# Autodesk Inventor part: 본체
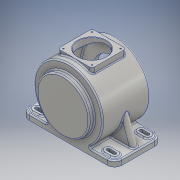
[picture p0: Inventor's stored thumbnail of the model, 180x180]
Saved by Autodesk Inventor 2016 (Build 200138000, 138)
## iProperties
Created: 2015-06
Part Number: 본체
Material: 알루미늄 6061
Document SubType Name: Modeling
Designer: Administrator
Density: 2.7 g/cm^3
Appearance: 알루미늄 - 평지
Mass: 3261.14 g
Surface Area: 2303.44 cm^2
Volume: 1207.83 cm^3
Author: Administrator
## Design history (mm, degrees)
sketch "스케치1"
  geometry: L1 (-115, 59)-(115, 59); L2 (115, 59)-(115, -59); L3 (115, -59)-(-115, -59); L4 (-115, -59)-(-115, 59); 3 further points
  constraints: 8 end point, 2 midpoint, 2 parallel, 1 horizontal, 1 horizontal alignment, 1 perpendicular, 1 vertical alignment
  dimensions: "d0" = 230 distance between parallel lines of L2 L4; "d1" = 118 distance between parallel lines of L3 L1
extrude "돌출1" new body sketch "스케치1" distance "d2" = 14; taper "d3" = 0 deg
sketch "스케치2"
  geometry: L1 (115, 0)-(-115, 0) reference; L2 (115, 0)-(115, 14) reference; L3 (-115, 14)-(115, 14) reference; L4 (-115, 0)-(-115, 14) reference; C1 r 85 at (0, 85); 2 further points
  constraints: 1 centre point, 1 midpoint, 1 vertical alignment
  dimensions: "d4" = 85 distance from line of L1 C1.centre; "d5" = 170 diameter of C1
extrude "돌출2" join sketch "스케치2" stored distance "d6" = 118; taper "d7" = 0 deg
sketch "스케치3"
  geometry: C1 r 65 at (115, 85); A1 r 85 centre (115, 85) between (161.733, 14) and (68.267, 14) reference; 1 further point
  constraints: 1 centre point, 1 coincident
  dimensions: "d8" = 130 diameter of C1
extrude "돌출3" join sketch "스케치3" distance "d9" = 13; taper "d10" = 0 deg
sketch "스케치4"
  geometry: L1 (230, -14)-(161.733, -14) reference; L2 (230, 0)-(230, -14) reference; L3 (0, 0)-(230, 0) reference; L4 (0, 0)-(0, -14) reference; L5 (68.267, -14)-(0, -14) reference; C1 r 65 at (115, -85); A1 r 85 centre (115, -85) between (68.267, -14) and (161.733, -14) reference; 1 further point
  constraints: 1 centre point, 1 coincident
  dimensions: "d11" = 130 diameter of C1
extrude "돌출4" join sketch "스케치4" distance "d12" = 3; taper "d13" = 0 deg
sketch "스케치5"
  geometry: L1 (-115, 14)-(-46.733, 14) reference; L2 (-84.87, 80.297)-(-109, 14); L3 (-115, 14)-(-46.733, 14) reference; L4 (-115, 0)-(-115, 14) reference; L5 (115, 0)-(-115, 0) reference; L6 (115, 0)-(115, 14) reference; L7 (46.733, 14)-(115, 14) reference; C1 r 65 at (0, 85) reference; A1 r 85 centre (0, 85) between (46.733, 14) and (-46.733, 14) reference; A2 r 85 centre (0, 85) between (46.733, 14) and (-46.733, 14) reference; 1 further point
  constraints: 2 end point, 1 point on circle, 1 point on line
  dimensions: "d14" = 110 deg angle of L2 L1; "d15" = 6 distance from line of L2.end L4
feature "리브1" sketch "스케치5" dims "d16" = 1, "d17" = 15, "d18" = 0, "d19" = 0, "d20" = 1, "d21" = 1
node "작업 평면1"
sketch "스케치6"
  geometry: L1 (42.5, 42.5)-(-42.5, 42.5); L2 (-42.5, 42.5)-(-42.5, -42.5); L3 (-42.5, -42.5)-(42.5, -42.5); L4 (42.5, -42.5)-(42.5, 42.5); 3 further points
  constraints: 8 end point, 2 midpoint, 2 parallel, 2 perpendicular, 1 horizontal, 1 horizontal alignment, 1 vertical alignment
  dimensions: "d23" = 85 distance between parallel lines of L2 L4
extrude "돌출5" join sketch "스케치6" stored distance "d24" = 3; taper "d25" = 0 deg
sketch "스케치7"
  geometry: C1 r 35 at (0, 0); 1 further point
  constraints: 1 centre point, 1 coincident
  dimensions: "d26" = 70 diameter of C1
sketch "스케치8"
  geometry: L1 (-42.5, 158.612)-(42.5, 158.612) reference; L2 (42.5, 158.612)-(42.5, 158.612) reference; L3 (42.5, 158.612)-(-42.5, 158.612) reference; L4 (-42.5, 158.612)-(-42.5, 158.612) reference; L5 (-7.5, 80.297)-(7.5, 80.297) reference; L6 (7.5, 80.297)-(7.5, 14) reference; L7 (59, 14)-(7.5, 14) reference; L8 (59, 14)-(59, 14) reference; L9 (7.5, 14)-(59, 14) reference; L10 (7.5, 14)-(7.5, 80.297) reference; L11 (7.5, 80.297)-(-7.5, 80.297) reference; L12 (-7.5, 80.297)-(-7.5, 14) reference; L13 (-59, 14)-(-7.5, 14) reference; L14 (-59, 14)-(-59, 14) reference; L15 (-7.5, 14)-(-59, 14) reference; L16 (-7.5, 14)-(-7.5, 80.297) reference; L17 (-72, 150)-(-72, 20) reference; L18 (62, 20)-(62, 150) reference; L19 (-72, 85)-(62, 85); L20 (62, 132.5)-(51, 132.5); L21 (51, 132.5)-(51, 159); L22 (48, 162)-(-48, 162); L23 (-51, 159)-(-51, 117.911); L24 (-49.268, 115.192)-(-47.5, 114.368); L25 (-47.5, 114.368)-(-47.5, 108.5); L26 (-47.5, 108.5)-(-61.2, 108.5); L27 (-61.5, 108.2)-(-61.5, 100); L28 (-61.5, 100)-(-61.5, 100); L29 (-64.5, 97)-(-64.5, 85); A1 r 0.3 centre (-61.2, 108.2) between (-61.2, 108.5) and (-61.5, 108.2); A2 r 3 centre (-61.5, 97) between (-61.5, 100) and (-64.5, 97); A3 r 3 centre (-48, 159) between (-48, 162) and (-51, 159); A4 r 3 centre (48, 159) between (51, 159) and (48, 162); A5 r 3 centre (-48, 117.911) between (-51, 117.911) and (-49.268, 115.192); 2 further points
  constraints: 22 end point, 10 point on circle, 10 tangent, 7 perpendicular, 5 centre point, 4 point on line, 2 midpoint, 1 equal radius, 1 horizontal, 1 vertical
  dimensions: "d27" = 11 distance between parallel lines of L18 L21; "d28" = 95 diameter of L20 L19; "d29" = 154 diameter of L22 L19; "d30" = 102 distance between parallel lines of L21 L23; "d31" = 62 diameter of point (-51, 116) L19; "d32" = 115 deg angle of L24 L23; "d33" = 3 distance between parallel lines of L27 L29; "d34" = 14 distance between parallel lines of L25 L27; "d35" = 30 diameter of L28 L19; "d36" = 47 diameter of L26 L19; "d37" = 3.5 distance between parallel lines of L25 L23; "d38" = 0.3 radius of A1; "d39" = 3 radius of A2; "d40" = 3 radius of A3; "d96" = 3 radius of A5
revolve "회전1" sketch "스케치8" stored, may be unused: angle "d41" = 90 deg
extrude "돌출6" cut sketch "스케치7" distance "d42" = 50; taper "d43" = 0 deg
sketch "스케치9"
  geometry: L1 (42.5, -42.5)-(-42.5, -42.5) reference; L2 (42.5, 42.5)-(42.5, -42.5) reference; L3 (-42.5, -42.5)-(-42.5, 42.5) reference; L4 (-42.5, 42.5)-(42.5, 42.5) reference; L5 (-35.5, -35.5)-(35.5, -35.5); L6 (35.5, -35.5)-(35.5, 35.5); L7 (35.5, 35.5)-(-35.5, 35.5); L8 (-35.5, 35.5)-(-35.5, -35.5); 5 further points
  constraints: 8 end point, 4 coincident, 3 other
  dimensions: "d44" = 71 distance between parallel lines of L8 L6
hole "구멍1" sketch "스케치9" at (35.5, -35.5), (-35.5, -35.5), (-35.5, 35.5), (35.5, 35.5) diameter "d45" = 3.242; stored, may be unused: countersink angle "d49" = 90 deg, drill point angle "d51" = 118 deg; dims "d46" = 10, "d47" = 4, "d48" = 2, "d50" = 13
chamfer "모따기1" distance "d52" = 1; stored, may be unused: second distance "d53" = 2, angle "d54" = 45 deg
fillet "모깎기1" dims "d56" = 7
sketch "스케치10"
  geometry: L1 (115, 59)-(115, -59) reference; L2 (115, -59)-(-115, -59) reference; L3 (-115, -59)-(-115, 59) reference; L4 (-115, 59)-(115, 59) reference; L5 (-97, 41)-(-81, 41); L6 (-97, 32)-(-81, 32); L7 (-81, 50)-(-97, 50); L8 (-115, 0)-(115, 0); L9 (-115, 59)-(115, 59) reference; L10 (0, 59)-(0, -59); L11 (115, -59)-(-115, -59) reference; L12 (-97, -41)-(-81, -41); L13 (-81, -50)-(-97, -50); L14 (-97, -32)-(-81, -32); L15 (97, -32)-(81, -32); L16 (97, -41)-(81, -41); L17 (81, -50)-(97, -50); L18 (97, 32)-(81, 32); L19 (81, 50)-(97, 50); L20 (97, 41)-(81, 41); A1 r 9 centre (-97, 41) between (-97, 50) and (-97, 32); A2 r 9 centre (-81, 41) between (-81, 32) and (-81, 50); A3 r 9 centre (-97, -41) between (-97, -32) and (-97, -50); A4 r 9 centre (-81, -41) between (-81, -50) and (-81, -32); A5 r 9 centre (81, -41) between (81, -32) and (81, -50); A6 r 9 centre (97, -41) between (97, -50) and (97, -32); A7 r 9 centre (81, 41) between (81, 50) and (81, 32); A8 r 9 centre (97, 41) between (97, 32) and (97, 50); 5 further points
  constraints: 36 end point, 21 symmetric about line, 16 point on circle, 8 centre point, 5 midpoint, 4 tangent, 1 horizontal, 1 parallel, 6 other
  dimensions: "d57" = 16 distance of L5.end L5.start; "d58" = 18 distance between parallel lines of L6 L7; "d59" = 18 distance from line of L5.start L3; "d60" = 18 distance from line of point (-89, 41) L4
extrude "돌출7" join sketch "스케치10" distance "d61" = 3; taper "d62" = 0 deg
sketch "스케치11"
  geometry: L1 (115, 59)-(115, -59) reference; L2 (115, -59)-(-115, -59) reference; L3 (-115, -59)-(-115, 59) reference; L4 (-115, 59)-(115, 59) reference; L5 (-97, 50)-(-81, 50) reference; L6 (-81, 32)-(-97, 32) reference; L7 (-81, -50)-(-97, -50) reference; L8 (-97, -32)-(-81, -32) reference; L9 (-46.733, -7.5)-(-109, -7.5) reference; L10 (-109, -7.5)-(-109, 7.5) reference; L11 (-109, 7.5)-(-46.733, 7.5) reference; L12 (-46.733, 7.5)-(-46.733, 59) reference; L13 (-46.733, 59)-(-115, 59) reference; L14 (-115, 59)-(-115, -59) reference; L15 (-115, -59)-(-46.733, -59) reference; L16 (-46.733, -59)-(-46.733, -7.5) reference; L17 (97, -50)-(81, -50) reference; L18 (81, -32)-(97, -32) reference; L19 (81, 50)-(97, 50) reference; L20 (97, 32)-(81, 32) reference; L21 (109, -7.5)-(46.733, -7.5) reference; L22 (46.733, -7.5)-(46.733, -59) reference; L23 (46.733, -59)-(115, -59) reference; L24 (115, -59)-(115, 59) reference; L25 (115, 59)-(46.733, 59) reference; L26 (46.733, 59)-(46.733, 7.5) reference; L27 (46.733, 7.5)-(109, 7.5) reference; L28 (109, 7.5)-(109, -7.5) reference; L29 (-81, 45)-(-97, 45); L30 (-97, 37)-(-81, 37); L31 (-81, -45)-(-97, -45); L32 (-97, -37)-(-81, -37); L33 (97, 45)-(81, 45); L34 (81, 37)-(97, 37); L35 (97, -45)-(81, -45); L36 (81, -37)-(97, -37); A1 r 9 centre (-97, 41) between (-97, 50) and (-97, 32) reference; A2 r 9 centre (-81, 41) between (-81, 32) and (-81, 50) reference; A3 r 9 centre (-81, -41) between (-81, -50) and (-81, -32) reference; A4 r 9 centre (-97, -41) between (-97, -32) and (-97, -50) reference; A5 r 9 centre (97, -41) between (97, -50) and (97, -32) reference; A6 r 9 centre (81, -41) between (81, -32) and (81, -50) reference; A7 r 9 centre (81, 41) between (81, 50) and (81, 32) reference; A8 r 9 centre (97, 41) between (97, 32) and (97, 50) reference; A9 r 4 centre (-97, 41) between (-97, 45) and (-97, 37); A10 r 4 centre (-81, 41) between (-81, 37) and (-81, 45); A11 r 4 centre (-81, -41) between (-81, -45) and (-81, -37); A12 r 4 centre (-97, -41) between (-97, -37) and (-97, -45); A13 r 4 centre (81, 41) between (81, 45) and (81, 37); A14 r 4 centre (97, 41) between (97, 37) and (97, 45); A15 r 4 centre (97, -41) between (97, -45) and (97, -37); A16 r 4 centre (81, -41) between (81, -37) and (81, -45); 1 further point
  constraints: 16 end point, 16 point on circle, 8 centre point, 3 equal radius, 12 other
  dimensions: "d63" = 8 distance between parallel lines of L30 L29
extrude "돌출11" cut sketch "스케치11" stored distance "d86" = 124; taper "d87" = 0 deg
sketch "스케치12"
  geometry: C1 r 65 at (0, 0) reference; A1 r 55 centre (0, 0) between (0, -55) and (55, 0); 3 further points
  constraints: 4 point on circle, 2 horizontal alignment, 2 vertical alignment, 1 centre point, 1 coincident
  dimensions: "d66" = 110 diameter of A1
hole "구멍2" sketch "스케치12" at (0, -55), (55, 0), (0, 55), (-55, 0) diameter "d67" = 3.242; stored, may be unused: countersink angle "d71" = 90 deg, drill point angle "d73" = 118 deg; dims "d68" = 10, "d69" = 4, "d70" = 2, "d72" = 13
sketch "스케치13"
  geometry: L1 (-115, 0)-(115, 0) reference; L2 (0, 85)-(85, 85); L3 (0, 85)-(77.036, 120.923); A1 r 85 centre (0, 85) between (46.733, 14) and (-46.733, 14) reference; 2 further points
  constraints: 4 end point, 2 point on circle, 1 coincident, 1 horizontal
  dimensions: "d74" = 25 deg angle of L2 L3
node "작업 평면2"
sketch "스케치14"
  geometry: 3 further points
  constraints: 1 coincident, 1 other
extrude "돌출9" join sketch "스케치14" stored distance "d75" = 0.5; taper "d76" = 0 deg
chamfer "모따기2" distance "d80" = 1; stored, may be unused: second distance "d81" = 2, angle "d82" = 45 deg
fillet "모깎기3" dims "d84" = 18
fillet "모깎기5" dims "d88" = 3
fillet "모깎기6" dims "d89" = 7.5
fillet "모깎기8" dims "d91" = 3
fillet "모깎기9" dims "d92" = 3
fillet "모깎기10" dims "d93" = 3
fillet "모깎기11" dims "d94" = 3
fillet "모깎기12" dims "d95" = 3
fillet "모깎기13" dims "d97" = 3
node "솔리드1"
mirror "대칭1"
node "투영된 루프1"
node "투영된 루프2"
node "투영된 루프3"
node "투영된 루프4"
node "투영된 루프5"
node "투영된 루프6"
node "투영된 루프7"
node "투영된 루프8"
other parameters: "d22" = -173
